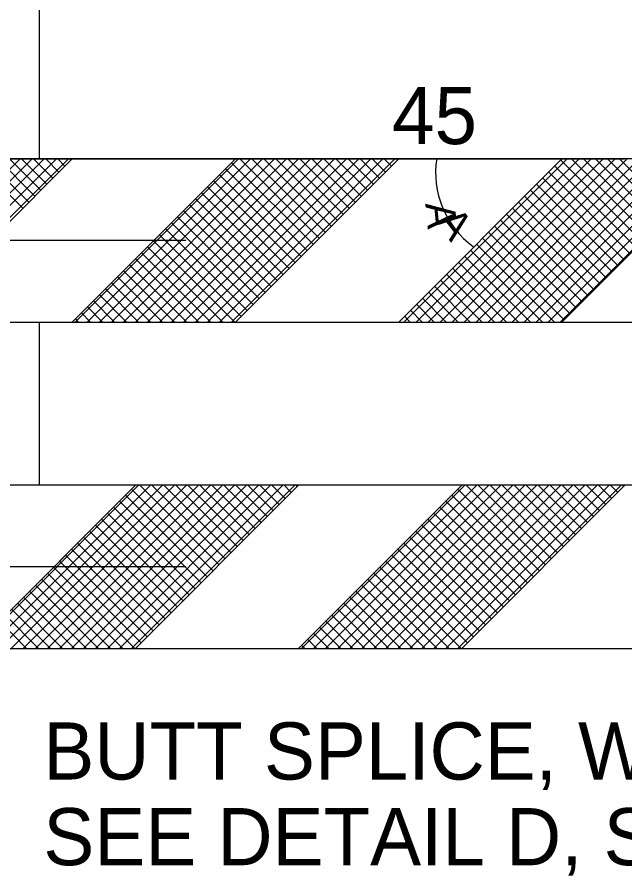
# Model space of a CAD drawing. Extents: x -4 to 901, y -468 to 720.
# Drawn here: x 421.8 to 457.6, y 595.4 to 645.9 of the extents above; entities that cross this region are included whole.
import ezdxf

# ---------------------------------------------------------------- set-up
doc = ezdxf.new("R2010")
doc.units = 0
doc.layers.add('2', color=7, linetype='Continuous')
doc.layers.add('3', color=7, linetype='Continuous')

msp = doc.modelspace()

# ---------------------------------------------------------------- linework, layer by layer
at = {"layer": '2'}
for p, q in [((406.5445, 637.595125), (457.5465, 637.595125)), ((415.4525, 627.995125), (425.0525, 637.595125)), ((425.0525, 627.995125), (434.6525, 637.595125)), ((425.0525, 627.995125), (434.6525, 637.595125)), ((434.6525, 627.995125), (444.2525, 637.595125)), ((444.2525, 627.995125), (453.8525, 637.595125)), ((453.8525, 627.995125), (463.4525, 637.595125)), ((431.7345, 632.795125), (397.6465, 632.795125)), ((419.1665, 608.795125), (428.7665, 618.395125)), ((419.1665, 608.795125), (428.7665, 618.395125)), ((419.1665, 608.795125), (428.7665, 618.395125)), ((424.3045, 613.933125), (428.7665, 618.395125)), ((428.7665, 608.795125), (438.3665, 618.395125)), ((438.3665, 608.795125), (447.9665, 618.395125)), ((438.3665, 608.795125), (447.9665, 618.395125)), ((438.3665, 608.795125), (447.9665, 618.395125)), ((438.3665, 608.795125), (447.9665, 618.395125)), ((443.5045, 613.933125), (447.9665, 618.395125)), ((447.9665, 608.795125), (457.5665, 618.395125)), ((431.7345, 613.595125), (397.6465, 613.595125))]:
    msp.add_line(p, q, dxfattribs=at)
for points in [[(423.1045, 647.195125), (423.1045, 637.595125)], [(412.39225, 627.995125), (421.99225, 637.595125)], [(413.09925, 627.995125), (422.69925, 637.595125)], [(413.80675, 627.995125), (423.40675, 637.595125)], [(414.51375, 627.995125), (424.11375, 637.595125)], [(415.22075, 627.995125), (424.82075, 637.595125)], [(422.148, 634.690375), (419.24325, 637.595125)], [(422.5015, 635.044375), (419.95075, 637.595125)], [(422.855, 635.397875), (420.65775, 637.595125)], [(423.2085, 635.751375), (421.36475, 637.595125)], [(423.562, 636.104875), (422.07175, 637.595125)], [(423.9155, 636.458375), (422.77875, 637.595125)], [(424.269, 636.811875), (423.48575, 637.595125)], [(424.6225, 637.165375), (424.19275, 637.595125)], [(424.97625, 637.519125), (424.90025, 637.595125)], [(425.22875, 627.995125), (434.82875, 637.595125)], [(425.93575, 627.995125), (435.53575, 637.595125)], [(426.64275, 627.995125), (436.24275, 637.595125)], [(427.34975, 627.995125), (436.94975, 637.595125)], [(428.05675, 627.995125), (437.65675, 637.595125)], [(428.76375, 627.995125), (438.36375, 637.595125)], [(429.47075, 627.995125), (439.07075, 637.595125)], [(430.17825, 627.995125), (439.77825, 637.595125)], [(430.88525, 627.995125), (440.48525, 637.595125)], [(431.59225, 627.995125), (441.19225, 637.595125)], [(432.29925, 627.995125), (441.89925, 637.595125)], [(433.00675, 627.995125), (442.60675, 637.595125)], [(433.71375, 627.995125), (443.31375, 637.595125)], [(434.42075, 627.995125), (444.02075, 637.595125)], [(439.58, 632.922875), (434.90775, 637.595125)], [(439.9335, 633.276375), (435.61475, 637.595125)], [(440.2875, 633.629875), (436.32225, 637.595125)], [(440.641, 633.983375), (437.02925, 637.595125)], [(440.9945, 634.336875), (437.73625, 637.595125)], [(441.348, 634.690375), (438.44325, 637.595125)], [(441.7015, 635.044375), (439.15075, 637.595125)], [(442.055, 635.397875), (439.85775, 637.595125)], [(442.4085, 635.751375), (440.56475, 637.595125)], [(442.762, 636.104875), (441.27175, 637.595125)], [(443.1155, 636.458375), (441.97875, 637.595125)], [(443.469, 636.811875), (442.68575, 637.595125)], [(443.8225, 637.165375), (443.39275, 637.595125)], [(444.17625, 637.519125), (444.10025, 637.595125)], [(444.5645, 627.995125), (454.1645, 637.595125)], [(445.2715, 627.995125), (454.8715, 637.595125)], [(445.9785, 627.995125), (455.5785, 637.595125)], [(446.686, 627.995125), (456.286, 637.595125)], [(447.393, 627.995125), (456.993, 637.595125)], [(448.1, 627.995125), (457.7, 637.595125)], [(448.807, 627.995125), (458.407, 637.595125)], [(449.514, 627.995125), (459.114, 637.595125)], [(450.2215, 627.995125), (459.8215, 637.595125)], [(450.9285, 627.995125), (460.5285, 637.595125)], [(451.6355, 627.995125), (461.2355, 637.595125)], [(452.3425, 627.995125), (461.9425, 637.595125)], [(453.05, 627.995125), (462.65, 637.595125)], [(453.757, 627.995125), (463.357, 637.595125)], [(458.584, 632.726625), (453.784, 637.526625)], [(458.9375, 633.080125), (454.4225, 637.595125)], [(459.291, 633.433625), (455.1295, 637.595125)], [(459.6445, 633.787125), (455.8365, 637.595125)], [(459.998, 634.140625), (456.5435, 637.595125)], [(460.35175, 634.494375), (457.251, 637.595125)], [(438.873, 632.215875), (434.07325, 637.015625)], [(439.2265, 632.569375), (434.42675, 637.369125)], [(458.23025, 632.372875), (453.43025, 637.172875)], [(438.5195, 631.862375), (433.71975, 636.662125)], [(457.52325, 631.665875), (452.72325, 636.465875)], [(457.87675, 632.019375), (453.07675, 636.819375)], [(438.166, 631.508375), (433.366, 636.308375)], [(457.16975, 631.312375), (452.36975, 636.112375)], [(437.459, 630.801375), (432.659, 635.601375)], [(437.8125, 631.154875), (433.0125, 635.954875)], [(456.816, 630.958625), (452.016, 635.758625)], [(437.1055, 630.447875), (432.3055, 635.247875)], [(456.109, 630.251625), (451.309, 635.051625)], [(456.4625, 630.605125), (451.6625, 635.405125)], [(436.398, 629.740875), (431.59825, 634.540625)], [(436.7515, 630.094375), (431.95175, 634.894125)], [(455.7555, 629.898125), (450.9555, 634.698125)], [(436.0445, 629.387375), (431.24475, 634.187125)], [(455.04825, 629.190875), (450.24825, 633.990875)], [(455.402, 629.544625), (450.602, 634.344625)], [(435.3375, 628.680375), (430.53775, 633.480125)], [(435.691, 629.033875), (430.89125, 633.833625)], [(454.69475, 628.837375), (449.89475, 633.637375)], [(434.984, 628.326375), (430.184, 633.126375)], [(453.98775, 628.130375), (449.18775, 632.930375)], [(454.34125, 628.483875), (449.54125, 633.283875)], [(434.6305, 627.972875), (429.8305, 632.772875)], [(453.416, 627.995125), (448.83425, 632.576875)], [(433.19425, 627.995125), (429.1235, 632.065875)], [(433.90125, 627.995125), (429.477, 632.419375)], [(452.7085, 627.995125), (448.4805, 632.223125)], [(432.48725, 627.995125), (428.77, 631.712375)], [(451.2945, 627.995125), (447.7735, 631.516125)], [(452.0015, 627.995125), (448.127, 631.869625)], [(431.07325, 627.995125), (428.063, 631.005375)], [(431.78025, 627.995125), (428.4165, 631.358875)], [(450.5875, 627.995125), (447.42, 631.162625)], [(430.36625, 627.995125), (427.7095, 630.651875)], [(449.173, 627.995125), (446.71275, 630.455375)], [(449.8805, 627.995125), (447.0665, 630.809125)], [(428.95175, 627.995125), (427.00225, 629.944625)], [(429.65875, 627.995125), (427.35575, 630.298125)], [(448.466, 627.995125), (446.35925, 630.101875)], [(428.24475, 627.995125), (426.64875, 629.591125)], [(447.052, 627.995125), (445.65225, 629.394875)], [(447.759, 627.995125), (446.00575, 629.748375)], [(427.53775, 627.995125), (426.29525, 629.237625)], [(446.3445, 627.995125), (445.2985, 629.041125)], [(426.12325, 627.995125), (425.588, 628.530375)], [(426.83075, 627.995125), (425.94175, 628.884125)], [(445.6375, 627.995125), (444.945, 628.687625)], [(423.1045, 627.995125), (423.1045, 618.395125)], [(425.41625, 627.995125), (425.2345, 628.176875)], [(444.9305, 627.995125), (444.5915, 628.334125)], [(419.34275, 608.795125), (428.94275, 618.395125)], [(420.04975, 608.795125), (429.64975, 618.395125)], [(420.75675, 608.795125), (430.35675, 618.395125)], [(421.46375, 608.795125), (431.06375, 618.395125)], [(422.17075, 608.795125), (431.77075, 618.395125)], [(422.87775, 608.795125), (432.47775, 618.395125)], [(423.58475, 608.795125), (433.18475, 618.395125)], [(424.29225, 608.795125), (433.89225, 618.395125)], [(424.99925, 608.795125), (434.59925, 618.395125)], [(425.70625, 608.795125), (435.30625, 618.395125)], [(426.41325, 608.795125), (436.01325, 618.395125)], [(427.12075, 608.795125), (436.72075, 618.395125)], [(427.82775, 608.795125), (437.42775, 618.395125)], [(428.53475, 608.795125), (438.13475, 618.395125)], [(433.694, 613.722875), (429.02175, 618.395125)], [(434.0475, 614.076375), (429.72875, 618.395125)], [(434.401, 614.429875), (430.43575, 618.395125)], [(434.7545, 614.783375), (431.14275, 618.395125)], [(435.10825, 615.137125), (431.85025, 618.395125)], [(435.46175, 615.490625), (432.55725, 618.395125)], [(435.8155, 615.844375), (433.26475, 618.395125)], [(436.169, 616.197875), (433.97175, 618.395125)], [(436.5225, 616.551375), (434.67875, 618.395125)], [(436.876, 616.904875), (435.38575, 618.395125)], [(437.2295, 617.258375), (436.09275, 618.395125)], [(437.583, 617.611875), (436.79975, 618.395125)], [(437.9365, 617.965375), (437.50675, 618.395125)], [(438.29025, 618.319125), (438.21425, 618.395125)], [(438.54275, 608.795125), (448.14275, 618.395125)], [(439.24975, 608.795125), (448.84975, 618.395125)], [(439.95675, 608.795125), (449.55675, 618.395125)], [(440.66375, 608.795125), (450.26375, 618.395125)], [(441.37075, 608.795125), (450.97075, 618.395125)], [(442.07775, 608.795125), (451.67775, 618.395125)], [(442.78475, 608.795125), (452.38475, 618.395125)], [(443.49225, 608.795125), (453.09225, 618.395125)], [(444.19925, 608.795125), (453.79925, 618.395125)], [(444.90625, 608.795125), (454.50625, 618.395125)], [(445.61325, 608.795125), (455.21325, 618.395125)], [(446.32075, 608.795125), (455.92075, 618.395125)], [(447.02775, 608.795125), (456.62775, 618.395125)], [(447.73475, 608.795125), (457.33475, 618.395125)], [(452.894, 613.722875), (448.22175, 618.395125)], [(453.2475, 614.076375), (448.92875, 618.395125)], [(453.601, 614.429875), (449.63575, 618.395125)], [(453.9545, 614.783375), (450.34275, 618.395125)], [(454.30825, 615.137125), (451.05025, 618.395125)], [(454.66175, 615.490625), (451.75725, 618.395125)], [(455.0155, 615.844375), (452.46475, 618.395125)], [(455.369, 616.197875), (453.17175, 618.395125)], [(455.7225, 616.551375), (453.87875, 618.395125)], [(456.076, 616.904875), (454.58575, 618.395125)], [(456.4295, 617.258375), (455.29275, 618.395125)], [(456.783, 617.611875), (455.99975, 618.395125)], [(457.1365, 617.965375), (456.70675, 618.395125)], [(457.49025, 618.319125), (457.41425, 618.395125)], [(432.987, 613.015875), (428.18725, 617.815625)], [(433.3405, 613.369375), (428.54075, 618.169125)], [(452.187, 613.015875), (447.38725, 617.815625)], [(452.5405, 613.369375), (447.74075, 618.169125)], [(432.6335, 612.662375), (427.83375, 617.462125)], [(451.8335, 612.662375), (447.03375, 617.462125)], [(432.28, 612.308875), (427.48025, 617.108625)], [(451.47975, 612.308625), (446.68, 617.108375)], [(431.57275, 611.601625), (426.773, 616.401375)], [(431.9265, 611.955375), (427.12675, 616.755125)], [(450.7725, 611.601375), (445.97275, 616.401125)], [(451.12625, 611.955125), (446.3265, 616.754875)], [(431.21925, 611.248125), (426.4195, 616.047875)], [(450.419, 611.247875), (445.61925, 616.047625)], [(430.512, 610.540875), (425.71225, 615.340625)], [(430.8655, 610.894375), (426.06575, 615.694125)], [(449.712, 610.540875), (444.91225, 615.340625)], [(450.0655, 610.894375), (445.26575, 615.694125)], [(430.1585, 610.187375), (425.35875, 614.987125)], [(449.3585, 610.187375), (444.55875, 614.987125)], [(429.4515, 609.480375), (424.65175, 614.280125)], [(429.805, 609.833875), (425.00525, 614.633625)], [(448.6515, 609.480375), (443.85175, 614.280125)], [(449.005, 609.833875), (444.20525, 614.633625)], [(429.098, 609.126875), (424.29825, 613.926625)], [(448.298, 609.126875), (443.49825, 613.926625)], [(428.7445, 608.773375), (423.94475, 613.573125)], [(447.9445, 608.773375), (443.14475, 613.573125)], [(427.30825, 608.795125), (423.2375, 612.865875)], [(428.01525, 608.795125), (423.591, 613.219375)], [(446.50825, 608.795125), (442.4375, 612.865875)], [(447.21525, 608.795125), (442.791, 613.219375)], [(426.60125, 608.795125), (422.884, 612.512375)], [(445.80125, 608.795125), (442.084, 612.512375)], [(425.18725, 608.795125), (422.177, 611.805375)], [(425.89425, 608.795125), (422.5305, 612.158875)], [(444.38725, 608.795125), (441.377, 611.805375)], [(445.09425, 608.795125), (441.7305, 612.158875)], [(424.48025, 608.795125), (421.8235, 611.451875)], [(443.68025, 608.795125), (441.0235, 611.451875)], [(423.06575, 608.795125), (421.11625, 610.744625)], [(423.77275, 608.795125), (421.46975, 611.098125)], [(442.26575, 608.795125), (440.31625, 610.744625)], [(442.97275, 608.795125), (440.66975, 611.098125)], [(422.35875, 608.795125), (420.76275, 610.391125)], [(441.55875, 608.795125), (439.96275, 610.391125)], [(440.85175, 608.795125), (439.60925, 610.037625)], [(439.43725, 608.795125), (438.902, 609.330375)], [(440.14475, 608.795125), (439.25575, 609.684125)], [(438.73025, 608.795125), (438.5485, 608.976875)]]:
    msp.add_lwpolyline(points, dxfattribs=at)
for points in [[(405.1045, 637.595125), (405.1045, 627.995125), (536.7925, 627.995125), (536.7925, 637.595125)], [(405.1045, 618.395125), (405.1045, 608.795125), (536.7925, 608.795125), (536.7925, 618.395125)]]:
    msp.add_lwpolyline(points, close=True, dxfattribs=at)
msp.add_arc((451.815012, 636.792515), 5.390059, 171.0697778, 233.9321167, dxfattribs=at)

# ---------------------------------------------------------------- texts
for height, rotation, p in [(1.727796, 275.6473556, (445.81625, 634.966125)), (1.727688, 307.4831972, (446.4055, 633.875625))]:
    msp.add_text('A', height=height, rotation=rotation, dxfattribs=at).set_placement(p)
at = {"layer": '3'}
for s, p in [('45', (443.863, 638.465625)), ('BUTT SPLICE, WHEN REQUIRED,', (423.3495, 601.084125)), ('SEE DETAIL D, SHEET 2.', (423.3495, 596.044125))]:
    msp.add_text(s, height=3.359988, dxfattribs=at).set_placement(p)

doc.saveas('drawing.dxf')
